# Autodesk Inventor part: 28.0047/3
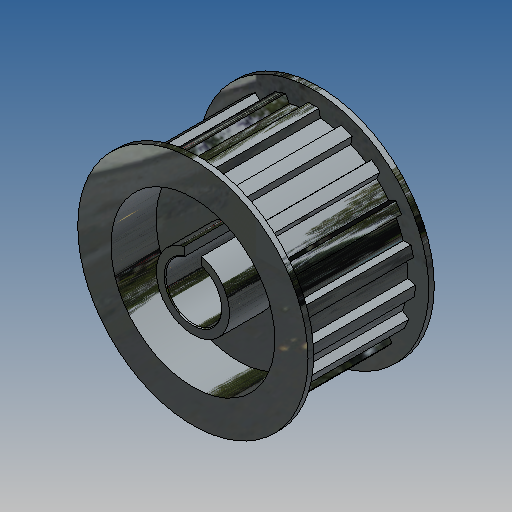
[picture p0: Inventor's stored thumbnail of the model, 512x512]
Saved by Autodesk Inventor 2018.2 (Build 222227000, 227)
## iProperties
Created: 2006-12
Document SubType Name: Modeling
Designer: Andy Moles
Material: Aluminum-6061
Part Number: 28.0047/3
Density: 2.71 g/cm^3
Description: T45 PULLEY 16mm
Appearance: Zinc
Author: Andy Moles
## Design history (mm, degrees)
sketch "Sketch1"
  geometry: L1 (-1.927, 26.982)-(-1.524, 29.17); L2 (1.927, 26.982)-(1.524, 29.17); L3 (11.073, 27.03)-(10.707, 24.842); L4 (15.084, 22.455)-(16.683, 23.977); L5 (19.077, 22.12)-(18.136, 20.071); L6 (21.534, 16.371)-(23.587, 17.23); L7 (25.254, 14.678)-(23.643, 13.144); L8 (25.717, 8.391)-(27.944, 8.508); L9 (28.652, 5.683)-(26.63, 4.755); L10 (27.049, -0.307)-(29.196, -0.889); L11 (28.945, -3.928)-(26.741, -4.085); L12 (25.484, -9.074)-(27.339, -10.286); L13 (26.084, -13.147)-(23.954, -12.569); L14 (21.157, -16.857)-(22.493, -18.635); L15 (20.429, -20.878)-(18.546, -19.693); L16 (14.537, -22.813)-(15.224, -24.929); L17 (12.543, -26.38)-(11.147, -24.648); L18 (6.342, -26.297)-(6.304, -28.522); L19 (3.298, -29.023)-(2.54, -26.931); L20 (-2.54, -26.931)-(-3.298, -29.023); L21 (-6.304, -28.522)-(-6.342, -26.297); L22 (-11.183, -24.631)-(-12.509, -26.396); L23 (-15.224, -24.929)-(-14.537, -22.813); L24 (-18.546, -19.693)-(-20.429, -20.878); L25 (-22.494, -18.635)-(-21.157, -16.856); L26 (-23.935, -12.604)-(-26.101, -13.113); L27 (-27.325, -10.322)-(-25.484, -9.074); L28 (-26.731, -4.15)-(-28.945, -3.928); L29 (-29.196, -0.89)-(-27.049, -0.307); L30 (-26.63, 4.756)-(-28.652, 5.685); L31 (-27.892, 8.674)-(-25.696, 8.455); L32 (-23.643, 13.144)-(-25.254, 14.679); L33 (-23.587, 17.23)-(-21.534, 16.371); L34 (-18.094, 20.109)-(-19.119, 22.083); L35 (-16.714, 23.955)-(-15.052, 22.477); L36 (-10.707, 24.842)-(-11.073, 27.03); L37 (-8.03, 28.085)-(-6.938, 26.146); L38 (6.938, 26.146)-(7.851, 28.135); A1 r 29.21 centre (0, 0) between (-16.714, 23.955) and (-19.119, 22.083); A2 r 27.051 centre (0, 0) between (-10.707, 24.842) and (-15.052, 22.477); A3 r 29.21 centre (0, 0) between (-8.03, 28.085) and (-11.073, 27.03); A4 r 27.051 centre (0, 0) between (-1.927, 26.982) and (-6.938, 26.146); A5 r 29.21 centre (0, 0) between (1.524, 29.17) and (-1.524, 29.17); A6 r 29.21 centre (0, 0) between (11.073, 27.03) and (7.851, 28.135); A7 r 29.21 centre (0, 0) between (19.077, 22.12) and (16.683, 23.977); A8 r 27.051 centre (0, 0) between (15.084, 22.455) and (10.707, 24.842); A9 r 27.051 centre (0, 0) between (21.534, 16.371) and (18.136, 20.071); A10 r 29.21 centre (0, 0) between (25.254, 14.678) and (23.587, 17.23); A11 r 27.051 centre (0, 0) between (25.717, 8.391) and (23.643, 13.144); A12 r 29.21 centre (0, 0) between (28.652, 5.683) and (27.944, 8.508); A13 r 27.051 centre (0, 0) between (27.049, -0.307) and (26.63, 4.755); A14 r 29.21 centre (0, 0) between (28.945, -3.928) and (29.196, -0.889); A15 r 27.051 centre (0, 0) between (25.484, -9.074) and (26.741, -4.085); A16 r 29.21 centre (0, 0) between (26.084, -13.147) and (27.339, -10.286); A17 r 27.051 centre (0, 0) between (21.157, -16.857) and (23.954, -12.569); A18 r 29.21 centre (0, 0) between (20.429, -20.878) and (22.493, -18.635); A19 r 27.051 centre (0, 0) between (14.537, -22.813) and (18.546, -19.693); A20 r 29.21 centre (0, 0) between (12.543, -26.38) and (15.224, -24.929); A21 r 27.051 centre (0, 0) between (6.342, -26.297) and (11.147, -24.648); A22 r 29.21 centre (0, 0) between (3.298, -29.023) and (6.304, -28.522); A23 r 27.051 centre (0, 0) between (-2.54, -26.931) and (2.54, -26.931); A24 r 29.21 centre (0, 0) between (-6.304, -28.522) and (-3.298, -29.023); A25 r 29.21 centre (0, 0) between (-15.224, -24.929) and (-12.509, -26.396); A26 r 29.21 centre (0, 0) between (-22.494, -18.635) and (-20.429, -20.878); A27 r 27.051 centre (0, 0) between (-11.183, -24.631) and (-6.342, -26.297); A28 r 27.051 centre (0, 0) between (-18.546, -19.693) and (-14.537, -22.813); A29 r 29.21 centre (0, 0) between (-27.325, -10.322) and (-26.101, -13.113); A30 r 27.051 centre (0, 0) between (-23.935, -12.604) and (-21.157, -16.856); A31 r 27.051 centre (0, 0) between (-26.731, -4.15) and (-25.484, -9.074); A32 r 29.21 centre (0, 0) between (-29.196, -0.89) and (-28.945, -3.928); A33 r 27.051 centre (0, 0) between (-26.63, 4.756) and (-27.049, -0.307); A34 r 29.21 centre (0, 0) between (-23.587, 17.23) and (-25.254, 14.679); A35 r 29.21 centre (0, 0) between (-27.892, 8.674) and (-28.652, 5.685); A36 r 27.051 centre (0, 0) between (-18.094, 20.109) and (-21.534, 16.371); A37 r 27.051 centre (0, 0) between (-23.643, 13.144) and (-25.696, 8.455); A38 r 27.051 centre (0, 0) between (6.938, 26.146) and (1.927, 26.982); 2 further points
  constraints: 77 point on circle, 76 end point, 38 centre point, 4 parallel, 2 coincident, 2 perpendicular
extrude "Extrusion1" new body sketch "Sketch1" stored distance "d19" = 33; taper "d20" = 0 deg
sketch "Sketch4"
  geometry: C1 r 33.02 at (0, 0); A1 r 27.051 centre (0, 0) between (6.938, 26.146) and (1.927, 26.982) reference
  constraints: 1 centre point, 1 coincident
  dimensions: "d24" = 66.04 diameter of C1
extrude "Extrusion3" join sketch "Sketch4" distance "d25" = 1.6; taper "d26" = 0 deg
workplane "Work Plane1"
sketch "Sketch3"
  geometry: L1 (-1.927, 26.982)-(-1.524, 29.17) reference; L2 (-8.03, 28.085)-(-6.938, 26.146) reference; L3 (-10.707, 24.842)-(-11.073, 27.03) reference; L4 (-16.714, 23.955)-(-15.052, 22.477) reference; L5 (-18.094, 20.109)-(-19.119, 22.083) reference; L6 (-23.587, 17.23)-(-21.534, 16.371) reference; L7 (-23.643, 13.144)-(-25.254, 14.679) reference; L8 (-27.892, 8.674)-(-25.696, 8.455) reference; L9 (-26.63, 4.756)-(-28.652, 5.685) reference; L10 (-29.196, -0.89)-(-27.049, -0.307) reference; L11 (-26.731, -4.15)-(-28.945, -3.928) reference; L12 (-27.325, -10.322)-(-25.484, -9.074) reference; L13 (-23.935, -12.604)-(-26.101, -13.113) reference; L14 (-22.494, -18.635)-(-21.157, -16.856) reference; L15 (-18.546, -19.693)-(-20.429, -20.878) reference; L16 (-15.224, -24.929)-(-14.537, -22.813) reference; L17 (-11.183, -24.631)-(-12.509, -26.396) reference; L18 (-6.304, -28.522)-(-6.342, -26.297) reference; L19 (-2.54, -26.931)-(-3.298, -29.023) reference; L20 (3.298, -29.023)-(2.54, -26.931) reference; L21 (6.342, -26.297)-(6.304, -28.522) reference; L22 (12.543, -26.38)-(11.147, -24.648) reference; L23 (14.537, -22.813)-(15.224, -24.929) reference; L24 (20.429, -20.878)-(18.546, -19.693) reference; L25 (21.157, -16.857)-(22.493, -18.635) reference; L26 (26.084, -13.147)-(23.954, -12.569) reference; L27 (25.484, -9.074)-(27.339, -10.286) reference; L28 (28.945, -3.928)-(26.741, -4.085) reference; L29 (27.049, -0.307)-(29.196, -0.889) reference; L30 (28.652, 5.683)-(26.63, 4.755) reference; L31 (25.717, 8.391)-(27.944, 8.508) reference; L32 (25.254, 14.678)-(23.643, 13.144) reference; L33 (21.534, 16.371)-(23.587, 17.23) reference; L34 (19.077, 22.12)-(18.136, 20.071) reference; L35 (15.084, 22.455)-(16.683, 23.977) reference; L36 (11.073, 27.03)-(10.707, 24.842) reference; L37 (6.938, 26.146)-(7.851, 28.135) reference; L38 (1.524, 29.17)-(1.927, 26.982) reference; C1 r 5.5 at (-12.643, -7.624) reference; A1 r 29.21 centre (0, 0) between (1.524, 29.17) and (-1.524, 29.17) reference; A2 r 27.051 centre (0, 0) between (-1.927, 26.982) and (-6.938, 26.146) reference; A3 r 29.21 centre (0, 0) between (-8.03, 28.085) and (-11.073, 27.03) reference; A4 r 27.051 centre (0, 0) between (-10.707, 24.842) and (-15.052, 22.477) reference; A5 r 29.21 centre (0, 0) between (-16.714, 23.955) and (-19.119, 22.083) reference; A6 r 27.051 centre (0, 0) between (-18.094, 20.109) and (-21.534, 16.371) reference; A7 r 29.21 centre (0, 0) between (-23.587, 17.23) and (-25.254, 14.679) reference; A8 r 27.051 centre (0, 0) between (-23.643, 13.144) and (-25.696, 8.455) reference; A9 r 29.21 centre (0, 0) between (-27.892, 8.674) and (-28.652, 5.685) reference; A10 r 27.051 centre (0, 0) between (-26.63, 4.756) and (-27.049, -0.307) reference; A11 r 29.21 centre (0, 0) between (-29.196, -0.89) and (-28.945, -3.928) reference; A12 r 27.051 centre (0, 0) between (-26.731, -4.15) and (-25.484, -9.074) reference; A13 r 29.21 centre (0, 0) between (-27.325, -10.322) and (-26.101, -13.113) reference; A14 r 27.051 centre (0, 0) between (-23.935, -12.604) and (-21.157, -16.856) reference; A15 r 29.21 centre (0, 0) between (-22.494, -18.635) and (-20.429, -20.878) reference; A16 r 27.051 centre (0, 0) between (-18.546, -19.693) and (-14.537, -22.813) reference; A17 r 29.21 centre (0, 0) between (-15.224, -24.929) and (-12.509, -26.396) reference; A18 r 27.051 centre (0, 0) between (-11.183, -24.631) and (-6.342, -26.297) reference; A19 r 29.21 centre (0, 0) between (-6.304, -28.522) and (-3.298, -29.023) reference; A20 r 27.051 centre (0, 0) between (-2.54, -26.931) and (2.54, -26.931) reference; A21 r 29.21 centre (0, 0) between (3.298, -29.023) and (6.304, -28.522) reference; A22 r 27.051 centre (0, 0) between (6.342, -26.297) and (11.147, -24.648) reference; A23 r 29.21 centre (0, 0) between (12.543, -26.38) and (15.224, -24.929) reference; A24 r 27.051 centre (0, 0) between (14.537, -22.813) and (18.546, -19.693) reference; A25 r 29.21 centre (0, 0) between (20.429, -20.878) and (22.493, -18.635) reference; A26 r 27.051 centre (0, 0) between (21.157, -16.857) and (23.954, -12.569) reference; A27 r 29.21 centre (0, 0) between (26.084, -13.147) and (27.339, -10.286) reference; A28 r 27.051 centre (0, 0) between (25.484, -9.074) and (26.741, -4.085) reference; A29 r 29.21 centre (0, 0) between (28.945, -3.928) and (29.196, -0.889) reference; A30 r 27.051 centre (0, 0) between (27.049, -0.307) and (26.63, 4.755) reference; A31 r 29.21 centre (0, 0) between (28.652, 5.683) and (27.944, 8.508) reference; A32 r 27.051 centre (0, 0) between (25.717, 8.391) and (23.643, 13.144) reference; A33 r 29.21 centre (0, 0) between (25.254, 14.678) and (23.587, 17.23) reference; A34 r 27.051 centre (0, 0) between (21.534, 16.371) and (18.136, 20.071) reference; A35 r 29.21 centre (0, 0) between (19.077, 22.12) and (16.683, 23.977) reference; A36 r 27.051 centre (0, 0) between (15.084, 22.455) and (10.707, 24.842) reference; A37 r 29.21 centre (0, 0) between (11.073, 27.03) and (7.851, 28.135) reference; A38 r 27.051 centre (0, 0) between (6.938, 26.146) and (1.927, 26.982) reference
workplane "Work Plane2"
sketch "Sketch5"
  geometry: C1 r 33.02 at (0, 0) reference; C2 r 10.5 at (0, 0); C3 r 23.5 at (0, 0)
  constraints: 2 centre point, 2 coincident
  dimensions: "d27" = 21 diameter of C2; "d28" = 47 diameter of C3
extrude "Extrusion4" cut sketch "Sketch5" distance "d29" = 12.954; taper "d30" = 0 deg
mirror "Mirror1"
sketch "Sketch6"
  geometry: L1 (-2.5, 7.599)-(-2.5, 10.3); L2 (-2.5, 10.3)-(2.5, 10.3); L3 (2.5, 10.3)-(2.5, 7.599); C1 r 10.5 at (0, 0) reference; A1 r 8 centre (0, 0) between (-2.5, 7.599) and (2.5, 7.599); 1 further point
  constraints: 6 end point, 2 point on circle, 1 centre point, 1 coincident, 1 midpoint, 1 parallel, 1 perpendicular, 1 vertical, 1 vertical alignment
  dimensions: "d31" = 16 diameter of A1 (= SHAFT_DIA); "d34" = 5 distance of L1.end L2.end (= SQUARE_KEY_SIZE); "d35" = 18.3 dimension on A1 L2 (= SHAFT_DIA + t2_KEYWAY_DEPTH)
extrude "Extrusion5" cut sketch "Sketch6" extent not by distance; stored distance "d32" = 12.954; taper "d33" = 0 deg
sketch "Sketch7"
  geometry: L1 (-2.04, 10.3)-(2.04, 10.3) reference; A1 r 10.5 centre (0, 0) between (2.04, 10.3) and (-2.04, 10.3) reference; 1 further point
extrude "Extrusion6" cut sketch "Sketch7" distance "d36" = 13; taper "d37" = 0 deg
mirror "Mirror2"
chamfer "Chamfer1" distance "d38" = 0.25; stored, may be unused: second distance "d39" = 2, angle "d40" = 45 deg
body "Solid1"
other parameters: "d1" = 2.159, "SHAFT_DIA" = 16 [user parameter; used in 2 equation terms], "SQUARE_KEY_SIZE" = 5 [user parameter; used in 1 equation term], "t2_KEYWAY_DEPTH" = 2.3 [user parameter; used in 1 equation term]
